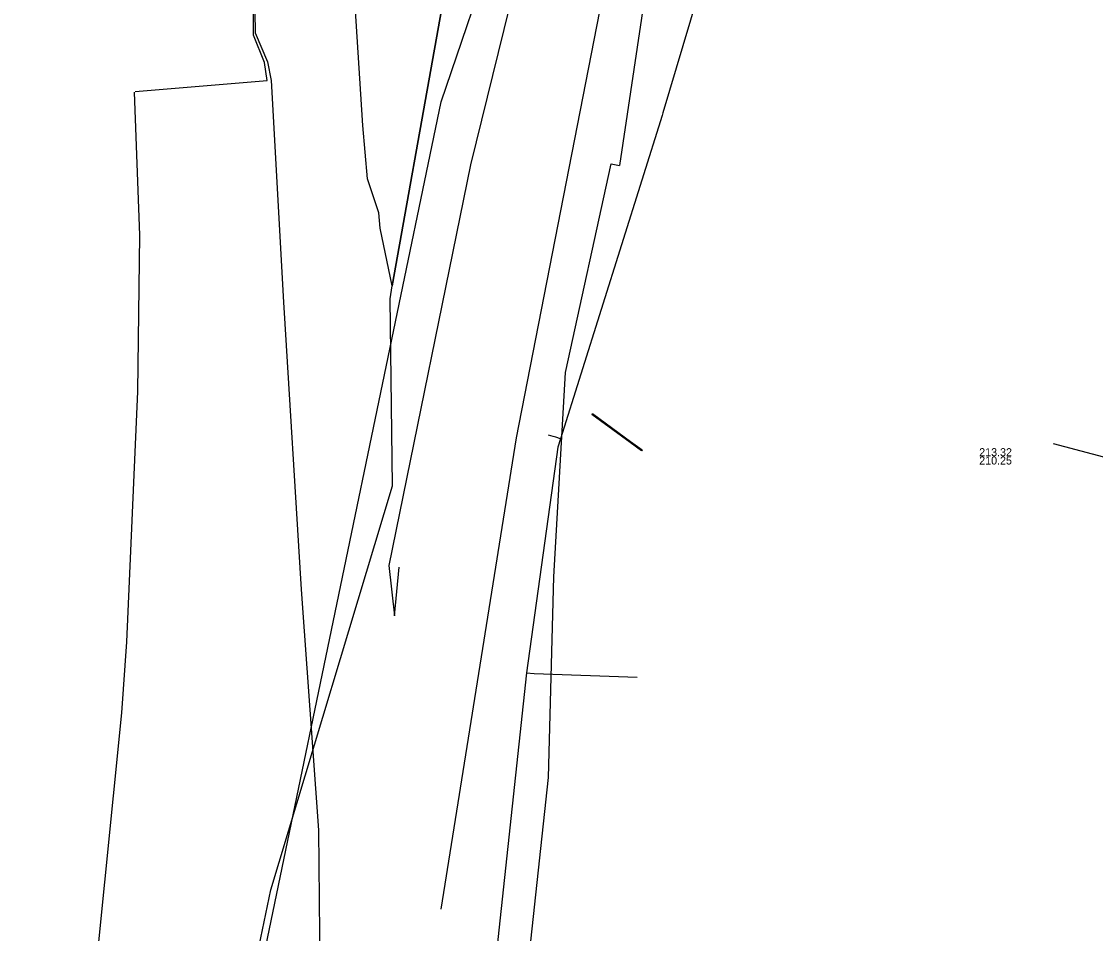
# Model space of a CAD drawing. Extents: x -599951 to -598963, y -1164095 to -1162939.
# Drawn here: x -599186.8 to -599079.4, y -1163707.4 to -1163616.2 of the extents above; entities that cross this region are included whole.
import ezdxf

# ---------------------------------------------------------------- set-up
doc = ezdxf.new("R2010")
doc.units = 0
for name, color, linetype in [('Level 1', 7, 'Continuous'), ('Level 3', 7, 'Continuous'), ('Vrstva 1', 7, 'Continuous'), ('Vrstva 12', 7, 'Continuous'), ('Vrstva 13', 7, 'Continuous'), ('Vrstva 55', 7, 'Continuous'), ('Vrstva 9', 7, 'Continuous')]:
    doc.layers.add(name, color=color, linetype=linetype)

msp = doc.modelspace()

# ---------------------------------------------------------------- linework, layer by layer
at = {"layer": 'Level 1'}
msp.add_lwpolyline([(-599173.8, -1163822.04), (-599166.01, -1163726.36), (-599144.8, -1163624.27), (-599116.33, -1163540.56), (-599088.36, -1163467.42), (-599053.62, -1163407.24), (-599018.44, -1163353.97), (-598979.36, -1163301.03), (-598963.215, -1163275.716)], dxfattribs=at)
at = {"layer": 'Level 3'}
msp.add_lwpolyline([(-599124.717, -1163659.066), (-599124.788, -1163659.163), (-599125.926, -1163658.331), (-599129.757, -1163655.531), (-599129.722, -1163655.483), (-599129.686, -1163655.434), (-599125.889, -1163658.209)], close=True, dxfattribs=at)
at = {"layer": 'Vrstva 1'}
for p, q in [((-599137.27, -1163657.85), (-599127.62, -1163608.39)), ((-599144.82, -1163704.97), (-599137.27, -1163657.85))]:
    msp.add_line(p, q, dxfattribs=at)
at = {"layer": 'Vrstva 13'}
for p, q in [((-599133.605, -1163657.715), (-599134.061, -1163657.569)), ((-599133.356, -1163657.793), (-599133.605, -1163657.715)), ((-599132.883, -1163657.941), (-599133.356, -1163657.793))]:
    msp.add_line(p, q, dxfattribs=at)
for points in [[(-599033.69, -1163418.68), (-599049.89, -1163446.95), (-599053.65, -1163460.69), (-599068.65, -1163494.5), (-599079.623, -1163519.036), (-599079.73, -1163519.27), (-599088.36, -1163538.62), (-599098.581, -1163562.017), (-599098.91, -1163562.77), (-599100.57, -1163566.48), (-599104.714, -1163575.654), (-599105.48, -1163577.35), (-599106.92, -1163580.56), (-599113.79, -1163595.64), (-599122.631, -1163625.369), (-599122.71, -1163625.62), (-599132.883, -1163657.941), (-599133.15, -1163658.79), (-599136.279, -1163681.357), (-599143.211, -1163745.819)], [(-599136.279, -1163681.357), (-599135.5, -1163681.42), (-599125.225, -1163681.768)]]:
    msp.add_lwpolyline(points, dxfattribs=at)
at = {"layer": 'Vrstva 55'}
for points in [[(-599056.04, -1163381.08), (-599054.78, -1163380.84), (-599043.79, -1163387.33), (-599020.488, -1163353.364), (-598995.31, -1163320.12), (-598993.82, -1163320.12), (-599016.324, -1163352.72), (-599037.484, -1163383.409), (-599040.79, -1163389.08), (-599058.044, -1163416.158), (-599062.52, -1163424.31), (-599076.715, -1163449.508), (-599093.194, -1163483.52), (-599100.75, -1163499.5), (-599108.949, -1163521.401), (-599120.598, -1163553.641), (-599128.23, -1163585.45), (-599132.47, -1163592.35), (-599141.869, -1163630.55), (-599150.024, -1163670.629), (-599149.47, -1163675.64), (-599149.011, -1163670.773)], [(-599081.76, -1163492.77), (-599085.01, -1163500.01), (-599089.419, -1163508.224), (-599102.253, -1163540.759), (-599114.485, -1163576.598), (-599124.443, -1163613.639), (-599126.99, -1163630.61)], [(-599167.231, -1163749.736), (-599164.09, -1163719.94), (-599163.502, -1163711.028), (-599161.82, -1163703.03), (-599149.662, -1163662.667), (-599149.9, -1163643.97), (-599149.72, -1163642.66), (-599141.225, -1163595.312), (-599149.72, -1163642.66), (-599150.889, -1163636.89), (-599151.042, -1163635.358), (-599152.176, -1163631.956), (-599152.636, -1163626.624), (-599153.984, -1163605.724)], [(-599175.395, -1163623.226), (-599162.201, -1163622.122), (-599162.465, -1163620.313), (-599163.569, -1163617.577), (-599163.745, -1163596.351), (-599163.392, -1163617.356), (-599162.156, -1163620.269), (-599161.81, -1163622.13), (-599160.56, -1163644.3), (-599158.79, -1163673), (-599157.055, -1163697.078), (-599156.945, -1163710.937), (-599156.578, -1163727.5), (-599157.054, -1163727.447)], [(-599186.765, -1163794.896), (-599184.748, -1163770.131), (-599181.786, -1163735.794), (-599176.721, -1163685.361), (-599176.249, -1163678.236), (-599175.133, -1163653.213), (-599174.919, -1163637.589), (-599175.457, -1163623.28)], [(-599162.057, -1164094.695), (-599165.35, -1164086.32), (-599166.73, -1164073.75), (-599165.047, -1164042.51), (-599160.24, -1164034.269), (-599157.836, -1164005.125), (-599157.45, -1163970.102), (-599156.162, -1163932.245), (-599156.04, -1163887.22), (-599152.39, -1163841.5), (-599149.466, -1163804.768), (-599147.296, -1163778.87), (-599143.812, -1163767.118), (-599138.093, -1163729.181), (-599134.088, -1163691.818), (-599133.543, -1163671.755), (-599132.377, -1163651.32), (-599127.82, -1163630.46), (-599126.99, -1163630.61)]]:
    msp.add_lwpolyline(points, dxfattribs=at)
at = {"layer": 'Vrstva 9'}
msp.add_line((-599083.61, -1163658.41), (-599031.82, -1163672.36), dxfattribs=at)

# ---------------------------------------------------------------- texts
at = {"layer": 'Vrstva 12'}
for s, p in [('213.32', (-599091.014, -1163659.687)), ('210.25', (-599091.014, -1163660.519))]:
    msp.add_text(s, height=0.8, dxfattribs=at).set_placement(p)

doc.saveas('drawing.dxf')
